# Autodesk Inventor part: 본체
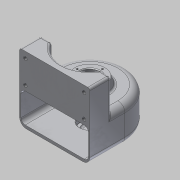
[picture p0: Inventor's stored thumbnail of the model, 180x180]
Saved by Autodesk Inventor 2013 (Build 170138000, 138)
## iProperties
Created: 2015-02
Part Number: 본체
Material: 알루미늄 6061
Document SubType Name: Modeling
Designer: Administrator
Density: 2.71 g/cm^3
Mass: 519.169 g
Surface Area: 717.843 cm^2
Volume: 191.575 cm^3
Author: Administrator
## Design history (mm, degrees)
sketch "스케치1"
  geometry: L1 (-50, -50)-(50, -50); L2 (50, -50)-(50, 0); L3 (-50, -50)-(-50, 0); A1 r 50 centre (0, 0) between (50, 0) and (-50, 0); 2 further points
  constraints: 6 end point, 2 midpoint, 2 point on circle, 2 tangent, 2 vertical, 1 centre point, 1 coincident, 1 horizontal, 1 vertical alignment
  dimensions: "d0" = 100 diameter of A1; "d1" = 50 distance from line of point (0, 0) L1
extrude "돌출1" new body sketch "스케치1" stored distance "d2" = 50; taper "d3" = 0 deg
sketch "스케치2"
  geometry: L1 (50, -50)-(-50, -50) reference; L2 (-50, -50)-(-50, 0) reference; L3 (50, 0)-(50, -50) reference; L4 (-48, 0)-(-48, -50); L5 (48, 0)-(48, -50); A1 r 50 centre (0, 0) between (50, 0) and (-50, 0) reference; A2 r 48 centre (0, 0) between (48, 0) and (-48, 0); 1 further point
  constraints: 4 end point, 2 perpendicular, 2 point on circle, 2 point on line, 2 tangent, 1 centre point, 1 coincident
  dimensions: "d4" = 96 diameter of A2
extrude "돌출2" cut sketch "스케치2" stored distance "d5" = 42; taper "d6" = 0 deg
sketch "스케치3"
  geometry: L1 (-50, -50)-(50, -50) reference; L2 (-50, -50)-(50, -50) reference; L3 (50, -50)-(50, 0) reference; L4 (-50, 0)-(-50, -50) reference; L5 (-50, -50)-(50, -50); L6 (50, -50)-(50, -20); L7 (50, -20)-(34.641, -20); L8 (-50, -50)-(-50, -20); L9 (-50, -20)-(-34.641, -20); A1 r 50 centre (0, 0) between (50, 0) and (-50, 0) reference; A2 r 40 centre (0, 0) between (-34.641, -20) and (34.641, -20)
  constraints: 10 end point, 2 collinear, 2 perpendicular, 2 point on circle, 2 point on line, 1 centre point, 1 coincident
  dimensions: "d7" = 80 diameter of A2; "d8" = 30 distance between parallel lines of L1 L7
extrude "돌출3" join sketch "스케치3" distance "d9" = 45; taper "d10" = 0 deg
sketch "스케치4"
  geometry: C1 r 25 at (0, 0); A1 r 40 centre (0, 0) between (-34.641, -20) and (34.641, -20) reference
  constraints: 1 centre point, 1 coincident
  dimensions: "d11" = 50 diameter of C1
extrude "돌출4" join sketch "스케치4" distance "d12" = 10; taper "d13" = 0 deg
hole "구멍1" diameter "d16" = 20; stored, may be unused: countersink angle "d20" = 90 deg, drill point angle "d22" = 118 deg; dims "d14" = 10, "d15" = 10, "d17" = 6, "d18" = 28, "d19" = 10, "d21" = 28.75
feature "면 기울기1" dims angle "d23" = 20 deg
sketch "스케치5"
  geometry: C1 r 20 at (0, 0); A1 r 50 centre (0, 0) between (50, 0) and (-50, 0) reference
  constraints: 1 centre point, 1 coincident
  dimensions: "d24" = 40 diameter of C1
extrude "돌출5" join sketch "스케치5" distance "d26" = 9; taper "d27" = 0 deg
hole "구멍2" diameter "d30" = 20; stored, may be unused: countersink angle "d34" = 90 deg, drill point angle "d36" = 0 deg; dims "d28" = 10, "d29" = 10, "d31" = 6, "d32" = 28, "d33" = 8, "d35" = 10
sketch "스케치6"
  geometry: C1 r 14 at (0, 0) reference; 1 further point
  constraints: 1 vertical alignment
  dimensions: "d37" = 18 distance of point (0, 18) C1.centre
hole "구멍3" sketch "스케치6" at (0, 18) diameter "d38" = 2.459; stored, may be unused: countersink angle "d42" = 90 deg, drill point angle "d44" = 118 deg; dims "d39" = 6, "d40" = 28, "d41" = 8, "d43" = 9
sketch "스케치7"
  geometry: L1 (100, 0)-(100, 95) reference; L2 (0, 95)-(100, 95) reference; 5 further points
  constraints: 2 horizontal alignment, 2 vertical alignment
  dimensions: "d49" = 9 distance from line of L2 point (91.75, 86); "d50" = 33 distance of point (91.75, 53) point (91.75, 86); "d51" = 83.5 distance of point (8.25, 86) point (91.75, 86); "d52" = 8.25 distance from line of point (91.75, 86) L1
hole "구멍4" sketch "스케치7" at (91.75, 86), (91.75, 53), (8.25, 86), (8.25, 53) diameter "d53" = 5.134; stored, may be unused: countersink angle "d57" = 90 deg, drill point angle "d59" = 118 deg; dims "d54" = 10, "d55" = 28, "d56" = 8, "d58" = 13
fillet "모깎기1" dims "d60" = 6, "d61" = 10
fillet "모깎기2" dims "d62" = 0.3
fillet "모깎기3" dims "d63" = 3
fillet "모깎기4" dims "d64" = 3
chamfer "모따기1" distance "d65" = 1; stored, may be unused: second distance "d66" = 2, angle "d67" = 45 deg
node "작업 평면1"
sketch "스케치8"
  geometry: L1 (40, -25)-(-40, -25) reference; 2 further points
  constraints: 1 coincident, 1 other
  dimensions: "d68" = 25 distance from line of point (0, 0) L1
feature "엠보싱1" sketch "스케치8" dims "d0" = 100, "d1" = 50, "d69" = 0.5, "d70" = 0
fillet "모깎기5" dims "d71" = 3
node "솔리드1"
pattern_circular "원형 패턴1" dims angle "d46" = 360 deg
node "투영된 루프1"
node "투영된 루프2"
